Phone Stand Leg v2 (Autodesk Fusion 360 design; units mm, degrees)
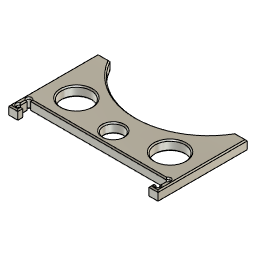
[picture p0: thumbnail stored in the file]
sketch "Sketch1" plane through (0, 0, 0) normal (0, 0, 1) x axis (1, 0, 0)
  line L1 (95.504, 0) -> (0, 0)
  line L2 (95.504, 57.15) -> (95.504, 0)
  line L3 (0, 57.15) -> (95.504, 57.15)
  line L4 (0, 0) -> (0, 57.15)
  line L5 (91.174, 9.652) -> (4.331, 9.652)
  line L6 (92.266, 4.267) -> (92.266, 8.56)
  line L7 (3.239, 8.56) -> (3.239, 4.267)
  line L8 (89.726, 0) -> (89.726, 3.175)
  line L9 (5.779, 0) -> (89.726, 0)
  line L10 (5.779, 3.175) -> (5.779, 0)
  line L11 (89.726, 3.175) -> (91.174, 3.175)
  line L12 (4.331, 3.175) -> (5.779, 3.175)
  arc A1 centre (3.239, 9.652) radius 1.092 clockwise from (3.239, 8.56) to (4.331, 9.652)
  arc A2 centre (3.239, 3.175) radius 1.092 clockwise from (4.331, 3.175) to (3.239, 4.267)
  arc A3 centre (92.266, 9.652) radius 1.092 clockwise from (91.174, 9.652) to (92.266, 8.56)
  arc A4 centre (92.266, 3.175) radius 1.092 clockwise from (92.266, 4.267) to (91.174, 3.175)
  point P1 (0, 0)
  point P2 (0, 0)
  point P8 (89.726, 0)
  point P6 (5.779, 3.175)
  point P3 (95.504, 0)
  point P5 (0, 57.15)
  point P11 (92.266, 9.652)
  point P12 (3.239, 9.652)
  horizontal L1
  vertical L2
  horizontal L3
  vertical L4
  coincident P1 P2
  horizontal L5
  vertical L6
  horizontal L11
  vertical L7
  vertical L8
  horizontal L9
  vertical L10
  coincident L1 P8
  coincident P6 L11
  collinear L11 L12
  dimension "d1" distance P2 P3 = 95.504
  dimension "d2" distance P2 P5 = 57.15
  dimension "d3" distance P11 P12 = 89.027
  dimension "d4" distance L1 L11 = 3.175
  dimension "d5" distance L5 L11 = 6.477
  dimension "d6" distance L4 L7 = 3.239
  dimension "d7" distance L7 L10 = 2.54
  dimension "d8" distance L6 L8 = 2.54
  dimension "d9" diameter A4 = 2.184
  dimension "d10" diameter A3 = 2.184
  dimension "d11" diameter A1 = 2.184
  dimension "d12" diameter A2 = 2.184
extrude "Extrude1" new body sketch "Sketch1" profile of L1 L2 L3 L4 L5 L6 L12 L7 L8 L10 A4 A3 A1 A2 along normal blind 6.35
sketch "Sketch2" plane through (0, 0, 6.35) normal (0, 0, 1) x axis (-1, 0, 0)
  line L1 (-89.726, 0) -> (-89.726, -3.175)
  line L2 (-95.504, 0) -> (-89.726, 0)
  line L3 (-95.504, -57.15) -> (-95.504, 0)
  line L4 (0, -57.15) -> (-95.504, -57.15)
  line L5 (0, 0) -> (0, -57.15)
  line L6 (-5.779, 0) -> (0, 0)
  line L7 (-5.779, -3.175) -> (-5.779, 0)
  line L8 (-4.331, -3.175) -> (-5.779, -3.175)
  line L9 (-3.239, -8.56) -> (-3.239, -4.267)
  line L10 (-91.174, -9.652) -> (-4.331, -9.652)
  line L11 (-92.266, -4.267) -> (-92.266, -8.56)
  line L12 (-89.726, -3.175) -> (-91.174, -3.175)
  line L13 (-87.884, -57.15) -> (-7.62, -57.15)
  arc A1 centre (-3.239, -3.175) radius 1.092 clockwise from (-4.331, -3.175) to (-3.239, -4.267)
  arc A2 centre (-3.239, -9.652) radius 1.092 clockwise from (-3.239, -8.56) to (-4.331, -9.652)
  arc A3 centre (-92.266, -9.652) radius 1.092 clockwise from (-91.174, -9.652) to (-92.266, -8.56)
  arc A4 centre (-92.266, -3.175) radius 1.092 clockwise from (-92.266, -4.267) to (-91.174, -3.175)
  arc A5 centre (-47.752, -80.0784) radius 46.22 clockwise from (-87.884, -57.15) to (-7.62, -57.15)
  circle C1 centre (-17.78, -25.527) radius 9.525
  circle C2 centre (-77.724, -25.527) radius 9.525
  circle C3 centre (-47.752, -19.177) radius 6.35
  point P23 (-87.884, -57.15)
  point P22 (-7.62, -57.15)
  point P6 (0, -57.15)
  point P5 (-95.504, -57.15)
  point P25 (-17.78, -25.527)
  point P26 (-77.724, -25.527)
  point P27 (-47.752, -19.177)
  coincident L4 P23
  coincident L4 P22
  dimension "d15" distance P6 P22 = 7.62
  dimension "d16" distance P5 P23 = 7.62
  dimension "d17" radius A5 = 46.22
  dimension "d18" diameter C1 = 19.05
  dimension "d19" diameter C2 = 19.05
  dimension "d20" diameter C3 = 12.7
  dimension "d21" distance L10 P25 = 15.875
  dimension "d22" distance L5 P25 = 17.78
  dimension "d23" distance L3 P26 = 17.78
  dimension "d24" distance L10 P26 = 15.875
  dimension "d25" distance L10 P27 = 9.525
  dimension "d27" distance L3 P27 = 47.752
extrude "Extrude2" cut sketch "Sketch2" profile of L4 A5 L13 C1 C2 C3 no distance stored
chamfer "Chamfer1" distance 0.762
